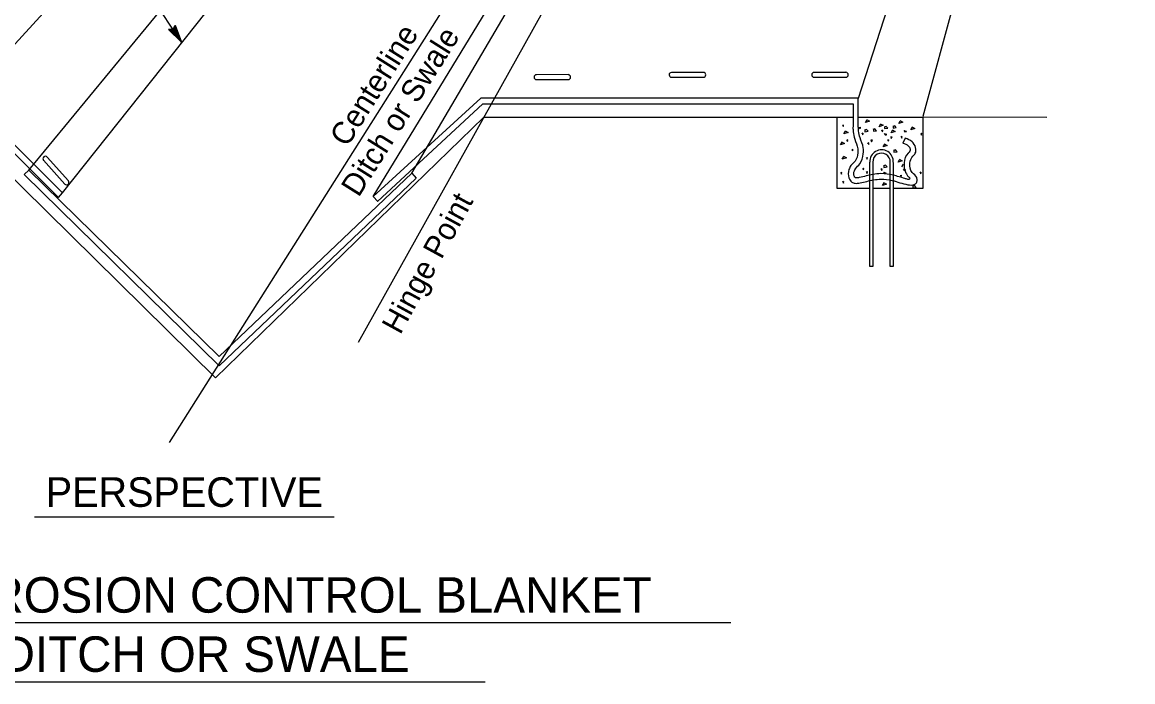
# Model space of a CAD drawing. Extents: x 6712486 to 6713732, y 1869200 to 1869925.
# Drawn here: x 6712663 to 6712975.5, y 1869199.8 to 1869385.4 of the extents above; entities that cross this region are included whole.
import ezdxf

# ---------------------------------------------------------------- set-up
doc = ezdxf.new("R2010")
doc.units = 0
for name, color, linetype in [('57 Undefined', 7, 'Continuous'), ('60 Nongeo Data', 7, 'Continuous'), ('63 Undefined', 7, 'Continuous')]:
    doc.layers.add(name, color=color, linetype=linetype)

msp = doc.modelspace()

# ---------------------------------------------------------------- linework, layer by layer
at = {"layer": '57 Undefined'}
for p, q in [((6712666.43, 1869246.24), (6712750.8, 1869246.24)), ((6712553.77, 1869216.45), (6712862.41, 1869216.45)), ((6712623.47, 1869199.8), (6712793.24, 1869199.8))]:
    msp.add_line(p, q, dxfattribs=at)
at = {"layer": '60 Nongeo Data'}
for p, q in [((6712592.16, 1869303.9), (6712842.3, 1869578.16)), ((6712757.6, 1869295.4), (6712915.04, 1869577.68)), ((6712916.52, 1869359), (6712975.47, 1869577.15)), ((6712664.82, 1869343.79), (6712850.81, 1869569.33)), ((6712674.37, 1869337.36), (6712854.97, 1869564.91)), ((6712772.67, 1869342.91), (6712903.42, 1869565.95)), ((6712761.77, 1869336.38), (6712898.99, 1869562.05)), ((6712704.43, 1869267.1), (6712878.15, 1869542.07)), ((6712707.85, 1869379.8), (6712619.78, 1869512.45)), ((6712941.44, 1869497.88), (6712898.16, 1869363.97)), ((6712816.62, 1869370.65), (6712807.66, 1869370.64)), ((6712845.61, 1869369.91), (6712854.63, 1869369.91)), ((6712854.63, 1869371.28), (6712845.68, 1869371.28)), ((6712885.73, 1869369.93), (6712894.75, 1869369.93)), ((6712894.75, 1869371.3), (6712885.79, 1869371.3)), ((6712807.6, 1869369.28), (6712816.62, 1869369.28)), ((6712892.27, 1869358.67), (6712896.86, 1869358.66)), ((6712898.07, 1869358.67), (6712916.58, 1869358.67)), ((6712900.23, 1869357.15), (6712900.68, 1869357.88)), ((6712901.42, 1869357.54), (6712900.23, 1869357.15)), ((6712900.57, 1869357.99), (6712901.42, 1869357.54)), ((6712909.61, 1869356.88), (6712910.06, 1869357.61)), ((6712909.95, 1869357.72), (6712910.8, 1869357.27)), ((6712894.07, 1869356.45), (6712893.76, 1869356.3)), ((6712893.76, 1869356.3), (6712893.81, 1869356.36)), ((6712893.81, 1869356.36), (6712894.04, 1869356.02)), ((6712894.04, 1869356.02), (6712894.1, 1869356.47)), ((6712894.19, 1869354.01), (6712894.65, 1869354.74)), ((6712895.38, 1869354.4), (6712894.19, 1869354.01)), ((6712894.53, 1869354.85), (6712895.38, 1869354.4)), ((6712898.84, 1869355.82), (6712898.52, 1869355.68)), ((6712898.52, 1869355.68), (6712898.58, 1869355.73)), ((6712898.58, 1869355.73), (6712898.81, 1869355.4)), ((6712898.81, 1869355.4), (6712898.86, 1869355.85)), ((6712900.57, 1869355.21), (6712900, 1869355.04)), ((6712900.12, 1869355.16), (6712900.12, 1869354.59)), ((6712900.12, 1869354.59), (6712901.02, 1869354.71)), ((6712901.02, 1869354.71), (6712900.57, 1869355.21)), ((6712902.94, 1869355.38), (6712902.37, 1869355.21)), ((6712902.49, 1869355.33), (6712902.49, 1869354.76)), ((6712902.49, 1869354.76), (6712903.39, 1869354.88)), ((6712903.39, 1869354.88), (6712902.94, 1869355.38)), ((6712904.07, 1869356), (6712904.52, 1869356.74)), ((6712905.25, 1869356.4), (6712904.07, 1869356)), ((6712904.41, 1869356.85), (6712905.25, 1869356.4)), ((6712905.09, 1869355.02), (6712904.78, 1869354.88)), ((6712904.78, 1869354.88), (6712904.84, 1869354.93)), ((6712904.84, 1869354.93), (6712905.06, 1869354.6)), ((6712905.06, 1869354.6), (6712905.12, 1869355.05)), ((6712906.11, 1869356.09), (6712905.55, 1869355.92)), ((6712905.66, 1869356.03), (6712905.66, 1869355.47)), ((6712905.66, 1869355.47), (6712906.56, 1869355.58)), ((6712906.56, 1869355.58), (6712906.11, 1869356.09)), ((6712907.46, 1869354.26), (6712907.91, 1869354.99)), ((6712908.64, 1869354.65), (6712907.46, 1869354.26)), ((6712907.79, 1869355.1), (6712908.64, 1869354.65)), ((6712908.48, 1869356.26), (6712907.92, 1869356.09)), ((6712908.03, 1869356.2), (6712908.03, 1869355.64)), ((6712908.03, 1869355.64), (6712908.93, 1869355.75)), ((6712908.93, 1869355.75), (6712908.48, 1869356.26)), ((6712910.8, 1869357.27), (6712909.61, 1869356.88)), ((6712911.08, 1869354.96), (6712911.36, 1869354.57)), ((6712911.08, 1869354.96), (6712911.7, 1869354.79)), ((6712911.36, 1869354.57), (6712911.76, 1869354.62)), ((6712911.76, 1869354.62), (6712911.7, 1869354.79)), ((6712913, 1869355.13), (6712913.45, 1869355.86)), ((6712914.19, 1869355.53), (6712913, 1869355.13)), ((6712913.34, 1869355.98), (6712914.19, 1869355.53)), ((6712893.2, 1869350.87), (6712893.66, 1869351.61)), ((6712894.39, 1869351.27), (6712893.2, 1869350.87)), ((6712893.54, 1869351.72), (6712894.39, 1869351.27)), ((6712895.26, 1869352.29), (6712894.95, 1869352.15)), ((6712894.95, 1869352.15), (6712895.01, 1869352.2)), ((6712895.01, 1869352.2), (6712895.23, 1869351.86)), ((6712895.23, 1869351.86), (6712895.29, 1869352.31)), ((6712899.55, 1869354.14), (6712899.24, 1869354)), ((6712899.24, 1869354), (6712899.29, 1869354.06)), ((6712899.29, 1869354.06), (6712899.52, 1869353.72)), ((6712899.52, 1869353.72), (6712899.57, 1869354.17)), ((6712901.22, 1869351.45), (6712900.91, 1869351.31)), ((6712900.91, 1869351.31), (6712900.97, 1869351.37)), ((6712900.97, 1869351.37), (6712901.19, 1869351.03)), ((6712901.19, 1869351.03), (6712901.25, 1869351.48)), ((6712902.26, 1869352.23), (6712901.75, 1869352.23)), ((6712901.81, 1869352.28), (6712901.98, 1869351.78)), ((6712901.98, 1869351.78), (6712902.26, 1869352.23)), ((6712905.54, 1869354.09), (6712905.82, 1869353.69)), ((6712905.54, 1869354.09), (6712906.16, 1869353.92)), ((6712905.56, 1869351.19), (6712906.41, 1869350.74)), ((6712905.82, 1869353.69), (6712906.21, 1869353.75)), ((6712906.21, 1869353.75), (6712906.16, 1869353.92)), ((6712906.76, 1869352.33), (6712906.45, 1869352.19)), ((6712906.45, 1869352.19), (6712906.51, 1869352.24)), ((6712906.51, 1869352.24), (6712906.74, 1869351.9)), ((6712906.74, 1869351.9), (6712906.79, 1869352.35)), ((6712907.8, 1869353.1), (6712907.3, 1869353.1)), ((6712907.35, 1869353.16), (6712907.52, 1869352.65)), ((6712907.52, 1869352.65), (6712907.8, 1869353.1)), ((6712910.53, 1869353.21), (6712910.22, 1869353.07)), ((6712910.28, 1869353.13), (6712910.5, 1869352.79)), ((6712910.5, 1869352.79), (6712910.56, 1869353.24)), ((6712910.56, 1869353.24), (6712910.5, 1869353.19)), ((6712916.08, 1869354.09), (6712915.77, 1869353.95)), ((6712915.82, 1869354.01), (6712916.05, 1869353.67)), ((6712916.05, 1869353.67), (6712916.1, 1869354.12)), ((6712916.1, 1869354.12), (6712916.05, 1869354.06)), ((6712896.7, 1869349.62), (6712896.39, 1869349.48)), ((6712896.39, 1869349.48), (6712896.45, 1869349.54)), ((6712896.45, 1869349.54), (6712896.67, 1869349.2)), ((6712896.67, 1869349.2), (6712896.73, 1869349.65)), ((6712905.22, 1869350.35), (6712905.67, 1869351.08)), ((6712906.41, 1869350.74), (6712905.22, 1869350.35)), ((6712908.7, 1869349.47), (6712908.13, 1869349.3)), ((6712908.25, 1869349.41), (6712908.25, 1869348.85)), ((6712908.25, 1869348.85), (6712909.15, 1869348.96)), ((6712909.15, 1869348.96), (6712908.7, 1869349.47)), ((6712668.96, 1869346.61), (6712674.95, 1869339.87)), ((6712675.98, 1869340.78), (6712670.02, 1869347.47)), ((6712893.72, 1869346.88), (6712894.18, 1869347.62)), ((6712894.91, 1869347.28), (6712893.72, 1869346.88)), ((6712894.06, 1869347.73), (6712894.91, 1869347.28)), ((6712900.76, 1869347.29), (6712900.45, 1869347.15)), ((6712900.45, 1869347.15), (6712900.51, 1869347.2)), ((6712900.51, 1869347.2), (6712900.74, 1869346.86)), ((6712900.74, 1869346.86), (6712900.79, 1869347.31)), ((6712901.48, 1869316.67), (6712901.47, 1869346.06)), ((6712902.32, 1869346.05), (6712902.34, 1869316.67)), ((6712905.92, 1869345.19), (6712905.35, 1869345.02)), ((6712905.46, 1869345.14), (6712905.46, 1869344.57)), ((6712906.37, 1869344.68), (6712905.92, 1869345.19)), ((6712907.24, 1869316.64), (6712907.23, 1869345.98)), ((6712908.09, 1869345.94), (6712908.07, 1869316.64)), ((6712909.42, 1869345.98), (6712909.87, 1869346.71)), ((6712910.6, 1869346.37), (6712909.42, 1869345.98)), ((6712909.76, 1869346.83), (6712910.6, 1869346.37)), ((6712910.5, 1869344.73), (6712910.96, 1869345.47)), ((6712772.67, 1869342.91), (6712773.83, 1869341.57)), ((6712893.59, 1869343.11), (6712893.28, 1869342.97)), ((6712893.28, 1869342.97), (6712893.34, 1869343.02)), ((6712893.34, 1869343.02), (6712893.56, 1869342.68)), ((6712893.56, 1869342.68), (6712893.62, 1869343.13)), ((6712899.75, 1869344.26), (6712899.44, 1869344.11)), ((6712899.49, 1869344.17), (6712899.72, 1869343.83)), ((6712899.72, 1869343.83), (6712899.78, 1869344.28)), ((6712899.78, 1869344.28), (6712899.72, 1869344.23)), ((6712900.77, 1869343.3), (6712900.45, 1869343.16)), ((6712900.51, 1869343.21), (6712900.74, 1869342.87)), ((6712900.74, 1869342.87), (6712900.79, 1869343.33)), ((6712900.79, 1869343.33), (6712900.74, 1869343.27)), ((6712904.9, 1869344.12), (6712904.58, 1869343.98)), ((6712904.58, 1869343.98), (6712904.64, 1869344.04)), ((6712904.64, 1869344.04), (6712904.87, 1869343.7)), ((6712904.87, 1869343.7), (6712904.92, 1869344.15)), ((6712905.34, 1869343.19), (6712905.62, 1869342.79)), ((6712905.34, 1869343.19), (6712905.96, 1869343.02)), ((6712905.46, 1869344.57), (6712906.37, 1869344.68)), ((6712905.62, 1869342.79), (6712906.02, 1869342.85)), ((6712906.02, 1869342.85), (6712905.96, 1869343.02)), ((6712910.34, 1869342.32), (6712910.03, 1869342.17)), ((6712910.08, 1869342.23), (6712910.31, 1869341.89)), ((6712910.31, 1869341.89), (6712910.37, 1869342.34)), ((6712910.37, 1869342.34), (6712910.31, 1869342.29)), ((6712910.89, 1869344.06), (6712911.17, 1869343.67)), ((6712910.89, 1869344.06), (6712911.51, 1869343.9)), ((6712911.17, 1869343.67), (6712911.56, 1869343.73)), ((6712911.56, 1869343.73), (6712911.51, 1869343.9)), ((6712915.88, 1869343.19), (6712915.57, 1869343.05)), ((6712915.63, 1869343.11), (6712915.85, 1869342.77)), ((6712915.85, 1869342.77), (6712915.91, 1869343.22)), ((6712915.91, 1869343.22), (6712915.85, 1869343.16)), ((6712894.12, 1869340.57), (6712893.81, 1869340.43)), ((6712893.81, 1869340.43), (6712893.86, 1869340.48)), ((6712893.86, 1869340.48), (6712894.09, 1869340.14)), ((6712894.09, 1869340.14), (6712894.15, 1869340.59)), ((6712905.03, 1869339.45), (6712905.48, 1869340.18)), ((6712906.21, 1869339.84), (6712905.03, 1869339.45)), ((6712905.37, 1869340.29), (6712906.21, 1869339.84)), ((6712914.05, 1869339.44), (6712913.48, 1869339.27)), ((6712913.6, 1869339.39), (6712913.6, 1869338.82)), ((6712913.6, 1869338.82), (6712914.5, 1869338.94)), ((6712914.5, 1869338.94), (6712914.05, 1869339.44)), ((6712673.19, 1869336.09), (6712674.37, 1869337.36)), ((6712761.77, 1869336.38), (6712763.04, 1869335)), ((6712902.34, 1869316.67), (6712901.48, 1869316.67)), ((6712908.07, 1869316.64), (6712907.24, 1869316.64))]:
    msp.add_line(p, q, dxfattribs=at)
for points in [[(6712674.37, 1869337.36), (6712647.2, 1869364.5), (6712542.99, 1869364.46)], [(6712898.11, 1869364), (6712792.07, 1869364.01), (6712761.77, 1869336.38)], [(6712898.2, 1869356.04), (6712898.16, 1869363.97)], [(6712544.42, 1869355.66), (6712544.4, 1869363.08), (6712646.3, 1869363.05), (6712673.19, 1869336.09)], [(6712762.98, 1869334.97), (6712792.63, 1869362.47), (6712896.76, 1869362.46), (6712896.78, 1869355.98)], [(6712548.67, 1869358.93), (6712642.64, 1869358.96), (6712717.35, 1869285.34), (6712792.86, 1869358.67), (6712892.16, 1869358.69), (6712892.17, 1869338.74), (6712901.48, 1869338.75)], [(6712908.06, 1869338.75), (6712916.49, 1869338.75), (6712916.49, 1869358.74), (6712951.31, 1869358.73)], [(6712664.82, 1869343.79), (6712663.59, 1869342.54), (6712718.46, 1869288.71)], [(6712664.82, 1869343.79), (6712718.46, 1869291.31)], [(6712772.67, 1869342.91), (6712718.46, 1869291.31)], [(6712718.46, 1869288.71), (6712773.83, 1869341.57)], [(6712902.32, 1869338.75), (6712907.24, 1869338.75)]]:
    msp.add_lwpolyline(points, dxfattribs=at)
for centre, radius, start, end in [((6712807.69, 1869369.96), 0.685, 92.5576, 270), ((6712816.61, 1869369.96), 0.686, 270, 90), ((6712845.71, 1869370.59), 0.685, 92.5576, 270), ((6712854.63, 1869370.59), 0.686, 270, 90), ((6712885.82, 1869370.62), 0.685, 92.5576, 270), ((6712894.75, 1869370.62), 0.686, 270, 90), ((6712669.53, 1869346.99), 0.685, 44.2481, 221.6905), ((6712675.46, 1869340.33), 0.686, 221.6905, 41.6905)]:
    msp.add_arc(centre, radius, start, end, dxfattribs=at)
for centre, major_axis in [((6712904.78, 1869346.18), (0, -3.31)), ((6712904.78, 1869346.14), (0, -2.45))]:
    msp.add_ellipse(centre, major_axis=major_axis, ratio=0.999991, start_param=1.510257, end_param=4.748244, dxfattribs=at)
at = {"layer": '63 Undefined'}
for p, q in [((6712704.17, 1869383.35), (6712704.17, 1869383.35)), ((6712706.02, 1869384.58), (6712706.02, 1869384.58)), ((6712707.85, 1869379.8), (6712707.85, 1869379.8)), ((6712911.43, 1869352.75), (6712910.75, 1869351.38))]:
    msp.add_line(p, q, dxfattribs=at)
msp.add_lwpolyline([(6712706.02, 1869384.58), (6712707.85, 1869379.8), (6712704.17, 1869383.35), (6712704.51, 1869383.37), (6712707.21, 1869380.76), (6712705.87, 1869384.27), (6712705.72, 1869383.96), (6712706.58, 1869381.72), (6712704.85, 1869383.38), (6712705.2, 1869383.4), (6712705.95, 1869382.68), (6712705.57, 1869383.65), (6712705.46, 1869383.41), (6712704.17, 1869383.35), (6712705.46, 1869383.41)], close=True, dxfattribs=at)
for points in [[(6712896.73, 1869355.83), (6712896.82, 1869354.59), (6712897.25, 1869352.53), (6712898.11, 1869349.82), (6712898.11, 1869348.63), (6712897.36, 1869346.35), (6712896.17, 1869345.05), (6712895.62, 1869343.97), (6712895.62, 1869341.59), (6712895.95, 1869340.99), (6712896.42, 1869340.42), (6712897.36, 1869340.07), (6712898.76, 1869340.18), (6712902.55, 1869341.04), (6712904.61, 1869341.26), (6712907.78, 1869340.87), (6712912.16, 1869339.68), (6712914, 1869339.73), (6712914.55, 1869340.13), (6712914.67, 1869340.39), (6712914.76, 1869340.78), (6712914.68, 1869341.69), (6712913.38, 1869343.1), (6712912.73, 1869345.7), (6712913.6, 1869347.76), (6712914.25, 1869348.52), (6712914.36, 1869350.12), (6712913.38, 1869351.77), (6712911.43, 1869352.75)], [(6712910.75, 1869351.38), (6712912.3, 1869350.61), (6712912.8, 1869349.75), (6712912.76, 1869349.13), (6712912.29, 1869348.57), (6712911.13, 1869345.83), (6712912, 1869342.35), (6712912.53, 1869341.77), (6712912.69, 1869341.62), (6712912.65, 1869341.21), (6712912.5, 1869341.15), (6712912.19, 1869341.19), (6712911.32, 1869341.43), (6712908.07, 1869342.37), (6712904.63, 1869342.8), (6712902.3, 1869342.55), (6712898.53, 1869341.69), (6712897.57, 1869341.62), (6712897.34, 1869341.71), (6712897.22, 1869341.85), (6712897.15, 1869341.97), (6712897.15, 1869343.61), (6712897.44, 1869344.18), (6712898.7, 1869345.56), (6712899.64, 1869348.38), (6712899.64, 1869350.06), (6712898.73, 1869352.92), (6712898.33, 1869354.8), (6712898.25, 1869355.94)]]:
    msp.add_spline(points, degree=3, dxfattribs=at)

# ---------------------------------------------------------------- texts
at = {"layer": '57 Undefined'}
for s, height, p in [('PERSPECTIVE', 8.3268, (6712669.63, 1869249.03)), ('TEMPORARY EROSION CONTROL BLANKET', 9.9921, (6712556.51, 1869219.25)), ('IN V-DITCH OR SWALE', 9.9921, (6712626.49, 1869202.59))]:
    msp.add_text(s, height=height, dxfattribs=at).set_placement(p)
at = {"layer": '60 Nongeo Data'}
for s, height, rotation, p in [('Centerline', 6.245, 57.8381, (6712754.45, 1869350.01)), ('Ditch or Swale', 6.2451, 57.8381, (6712757.65, 1869335.91)), ('Hinge Point', 6.2451, 61.3378, (6712769.36, 1869297.25))]:
    msp.add_text(s, height=height, rotation=rotation, dxfattribs=at).set_placement(p)

doc.saveas('drawing.dxf')
